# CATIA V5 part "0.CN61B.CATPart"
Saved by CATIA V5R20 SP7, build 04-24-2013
Part number: 0.CN61B
Material "Nessuno"
Bounding box of the stored display mesh (mm): x 0 to 149.213, y -131.181 to 0, z -56.919 to 41.584
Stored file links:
  C:\Users\designer2\Desktop\Ottobre 2022\25-10-2022\04\Yori Evo 48V\0.CN61B.CATPart
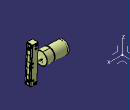
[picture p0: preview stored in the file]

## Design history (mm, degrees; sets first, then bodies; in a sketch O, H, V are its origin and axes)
AxisSystem1: origin (0, 0, 0), X (1, 0, 0), Y (0, 1, 0), Z (0, 0, 1)
Set1
  DatumSurface1
Body1 (main body), material "Nessuno"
